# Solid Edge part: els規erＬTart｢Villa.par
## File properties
Author: morva
Template: iso metric part.par
Last saved by: morva
Revision: 21
Application: Solid Edge
Density: 2712.000 kg/m^3
Accuracy: 0.990
Username: morva
Material: Aluminum, 6061-T6
Face Style: Aluminum
Fill Style: ANSI38(Aluminum)
Virtual Style: ANSI38(Aluminum)
Grouping: Metals\Aluminium Alloys
LibraryName: Materials
Coef. of Thermal Exp: 2.3e-05
Thermal Conductivity: 180.0
Specific Heat: 920.0
Modulus of Elasticity: 68947570000.0
Poisson's Ratio: 0.33
Yield Stress: 275790280.0
Ultimate Stress: 310264065.0
Elongation: 0.0
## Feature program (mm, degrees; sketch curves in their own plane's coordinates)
sketch for "unnamed Protrusion 1" #1 plane through (0, 0, 0) normal (0, 0, 1) x-axis (1, 0, 0)
  circle centre (0, 0) radius 10
sketch for "unnamed Protrusion 1" #2 plane through (0, 0, 0) normal (0, 0, 1) x-axis (1, 0, 0)
  circle centre (0, 0) radius 17.5
extrude "unnamed Protrusion 1" add finite 36 along +normal
sketch for "ExtrudedProtrusion_2" plane through (0, 0, 0) normal (0, 0, -1) x-axis (0, 1, 0)
  circle centre (0, 0) radius 20
extrude "ExtrudedProtrusion_2" add finite 15 along +normal
sketch for "ExtrudedProtrusion_4" plane through (0, 0, 0) normal (0, -1, 0) x-axis (1, 0, 0)
  line (-46, -69) -> (-46, -219)
  line (-51, -219) -> (-46, -219)
  line (-51, -69) -> (-51, -219)
  line (51, -69) -> (51, -219)
  line (51, -219) -> (46, -219)
  line (46, -69) -> (46, -219)
  dimension (linear) = 51
  dimension (linear) = 51
extrude "ExtrudedProtrusion_4" add finite 50 symmetric
sketch for "ExtrudedCutout_2" plane through (-51, 0, -136.5) normal (-1, 0, 0) x-axis (0, -1, 0)
  line (-5, -52.5) -> (-5, -82.5)
  line (-5, -82.5) -> (5, -82.5)
  line (5, -52.5) -> (5, -82.5)
extrude "ExtrudedCutout_2" cut finite 378.9977 symmetric
sketch for "ExtrudedCutout_3" plane through (-51, 0, -144) normal (-1, 0, 0) x-axis (0, -1, 0)
  line (-25, -45) -> (-25, -75)
  line (25, -75) -> (-25, -75)
  line (25, -45) -> (25, -75)
extrude "ExtrudedCutout_3" cut finite 2106.3891 symmetric
thread "Thread_1"  ThreadDepth = 35 mm
sketch for "ExtrudedProtrusion_5" plane through (-17.4162, 0, -15) normal (0, 0, -1) x-axis (0, -1, 0)
extrude "ExtrudedProtrusion_5" add finite 9 along +normal
sketch for "Hole_1" plane through (0, 0, -24) normal (0, 0, -1) x-axis (0, -1, 0)
hole "Hole_1" diameter 8 finite  VBottomAngle = 118 deg; ThreadDepth = 19 mm
fearecompute load "unnamed FEARecomputeLoad 1"
fearecompute load "unnamed FEARecomputeLoad 2"
fearecompute load "unnamed FEARecomputeLoad 3"
fearecompute load "unnamed FEARecomputeLoad 4"
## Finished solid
Body 1: solid body, 31 faces, 64 edges, 36 vertices.
  Faces by surface: cylinder 16, plane 14, cone 1
  Edges by curve: line 34, circle 27, intersection 3
Bounding box of the edges (mm): 102.000 x 50.000 x 249.495, from (-51, -25, -213.4949) to (51, 25, 36).
Cylindrical faces by radius (mm): R3.3235 x2, R5 x2, R10 x2, R17.5 x1, R20 x3, R25 x4, R46 x1, R51 x1
Conical faces (half-angle, radius in mm at the cone's reference point): 59 deg R3.3235 x1
Planar faces by outward normal: +x 2, +y 3, +z 3, -x 2, -y 3, -z 1
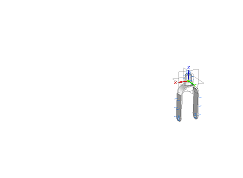
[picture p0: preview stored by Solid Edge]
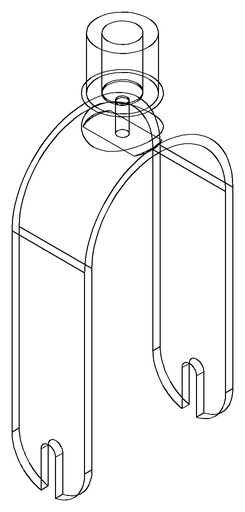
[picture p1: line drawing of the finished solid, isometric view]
